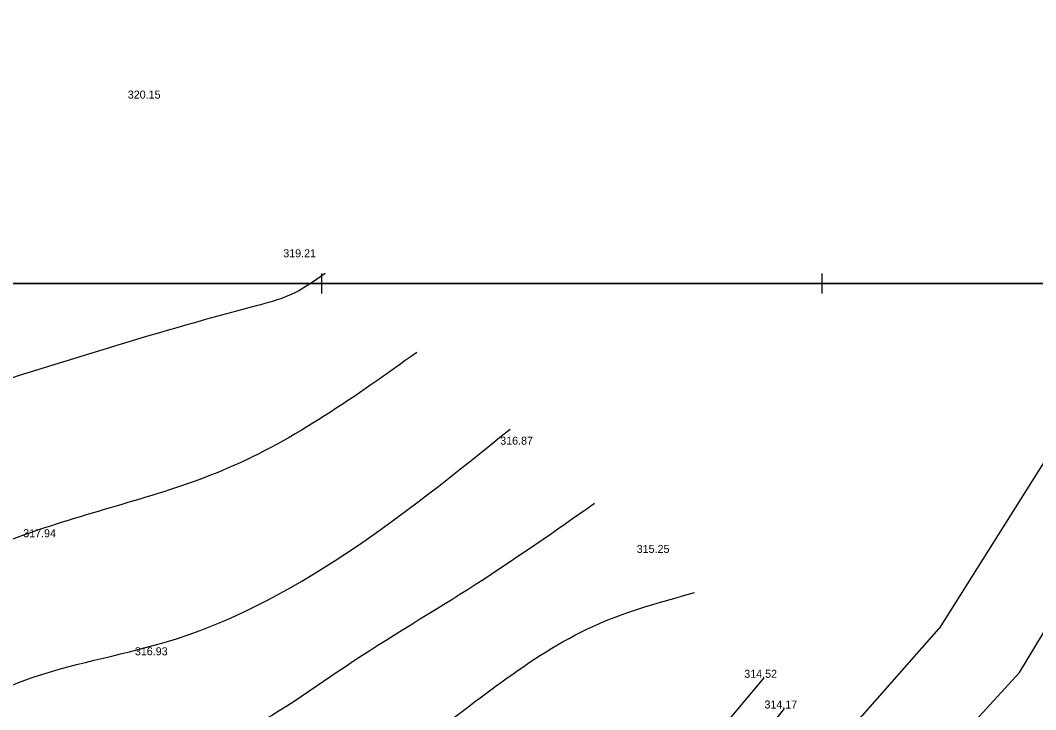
# Model space of a CAD drawing. Extents: x -504375 to -503125, y -1118000 to -1116474.
# Drawn here: x -503330.1 to -503228.6, y -1116542.6 to -1116473.7 of the extents above; entities that cross this region are included whole.
import ezdxf

# ---------------------------------------------------------------- set-up
doc = ezdxf.new("R2010")
doc.units = 0
for name, color, linetype in [('Druhy povrchů', 7, 'Continuous'), ('Podkladové mapy', 7, 'Continuous'), ('Síť dekadická', 7, 'Continuous'), ('Vrstva 34', 7, 'Continuous'), ('Vrstva 48', 7, 'Continuous'), ('Výškopis', 7, 'Continuous'), ('Výšky bodů plotr', 7, 'Continuous')]:
    doc.layers.add(name, color=color, linetype=linetype)

msp = doc.modelspace()

# ---------------------------------------------------------------- linework, layer by layer
at = {"layer": 'Druhy povrchů'}
msp.add_lwpolyline([(-503397.02, -1116689.72), (-503380.03, -1116674.83), (-503363.8, -1116660.36), (-503349.88, -1116645.16), (-503336.27, -1116629.65), (-503324.3, -1116612.68), (-503313.46, -1116603.24), (-503298.24, -1116588.67), (-503283.72, -1116572.76), (-503255.76, -1116539.4)], dxfattribs=at)
at = {"layer": 'Podkladové mapy'}
for p, q in [((-503200.022, -1116473.684), (-503238.29, -1116534.46)), ((-503230.27, -1116538.88), (-503192.069, -1116475.796)), ((-503246.43, -1116543.72), (-503238.29, -1116534.46)), ((-503265.72, -1116577.46), (-503230.27, -1116538.88))]:
    msp.add_line(p, q, dxfattribs=at)
at = {"layer": 'Síť dekadická'}
msp.add_lwpolyline([(-503125, -1116500), (-503125, -1117000), (-503750, -1117000), (-503750, -1116500)], close=True, dxfattribs=at)
at = {"layer": 'Vrstva 34'}
for p, q in [((-503300, -1116499), (-503300, -1116501)), ((-503250, -1116499), (-503250, -1116501)), ((-503299, -1116500), (-503301, -1116500)), ((-503249, -1116500), (-503251, -1116500))]:
    msp.add_line(p, q, dxfattribs=at)
msp.add_lwpolyline([(-503192.069, -1116500), (-503591.069, -1116500)], dxfattribs=at)
at = {"layer": 'Vrstva 48'}
for points in [[(-503299.657, -1116498.984), (-503303.211, -1116501.172), (-503306.53, -1116502.227), (-503337.887, -1116511.642)], [(-503290.496, -1116506.883), (-503309.393, -1116518.46), (-503328.29, -1116524.624), (-503350.268, -1116534.452), (-503366.085, -1116542.864), (-503383.317, -1116553.192), (-503389.867, -1116555.566), (-503411.101, -1116563.377)], [(-503423.262, -1116584.1), (-503400.51, -1116574.995), (-503371.603, -1116564.462), (-503355.454, -1116554.107), (-503339.126, -1116544.288), (-503329.669, -1116539.646), (-503315.72, -1116535.868), (-503281.172, -1116514.546)], [(-503272.713, -1116521.984), (-503284.552, -1116530.049), (-503297.613, -1116538.288), (-503309.659, -1116545.506), (-503317.719, -1116548.279), (-503326.116, -1116552.563), (-503330.483, -1116554.327), (-503334.009, -1116555.839), (-503347.343, -1116563.628), (-503356.881, -1116570.175), (-503363.037, -1116574.013), (-503376.976, -1116580.659), (-503385.521, -1116583.565), (-503391.321, -1116585.975), (-503395.157, -1116587.671), (-503409.879, -1116592.332), (-503411.663, -1116592.332), (-503418.533, -1116597.758), (-503431.06, -1116606.789)], [(-503388.833, -1116595.439), (-503375.375, -1116590.932), (-503361.776, -1116585.15), (-503355.232, -1116582.174), (-503340.443, -1116571.289), (-503331.009, -1116566.697), (-503323.444, -1116562.19), (-503319.644, -1116560.289), (-503302.365, -1116553.261), (-503290.126, -1116545.863), (-503272.293, -1116533.997), (-503262.721, -1116530.889)]]:
    msp.add_spline(points, degree=3, dxfattribs=at)
at = {"layer": 'Výškopis'}
msp.add_lwpolyline([(-503435.08, -1116738.92), (-503402.35, -1116702.54), (-503382.34, -1116679.28), (-503360.51, -1116664.43), (-503336.02, -1116637.68), (-503315.61, -1116615.01), (-503290.71, -1116587), (-503273.75, -1116568.11), (-503253.74, -1116542.47)], dxfattribs=at)

# ---------------------------------------------------------------- texts
at = {"layer": 'Výšky bodů plotr'}
for s, p in [('320.15 ', (-503319.37, -1116481.51)), ('319.21 ', (-503303.83, -1116497.37)), ('316.87 ', (-503282.15, -1116516.1)), ('317.94 ', (-503329.82, -1116525.35)), ('315.25 ', (-503268.51, -1116526.92)), ('316.93 ', (-503318.66, -1116537.15)), ('314.52 ', (-503257.76, -1116539.4)), ('314.17 ', (-503255.74, -1116542.47))]:
    msp.add_text(s, height=0.8, dxfattribs=at).set_placement(p)

doc.saveas('drawing.dxf')
